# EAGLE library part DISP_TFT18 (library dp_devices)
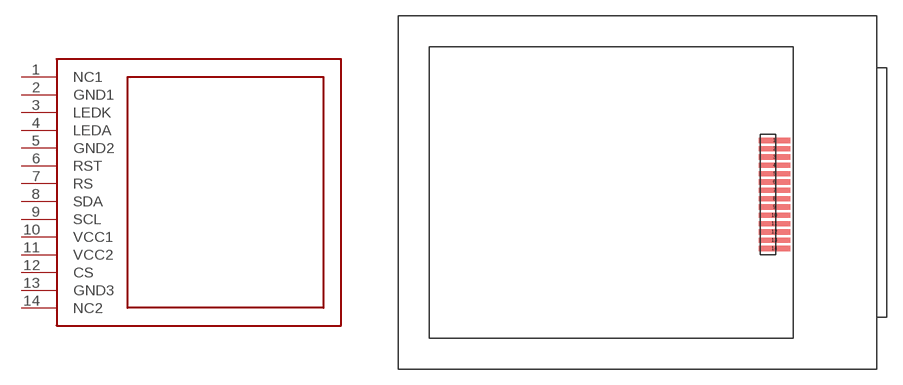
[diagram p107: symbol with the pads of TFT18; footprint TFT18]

Designator prefix -

## DISP_TFT18  [TFT18]
1  NC1
2  GND1
3  LEDK
4  LEDA
5  GND2
6  RST
7  RS
8  SDA
9  SCL
10  VCC1
11  VCC2
12  CS
13  GND3
14  NC2

## Footprint TFT18 (pad centres in mm)
smd 3 x 0.5: 1 13.2,5; 2 13.2,4.2; 3 13.2,3.4; 4 13.2,2.6; 5 13.2,1.8; 6 13.2,1; 7 13.2,0.2; 8 13.2,-0.6; 9 13.2,-1.4; 10 13.2,-2.2; 11 13.2,-3; 12 13.2,-3.8; 13 13.2,-4.6; 14 13.2,-5.4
